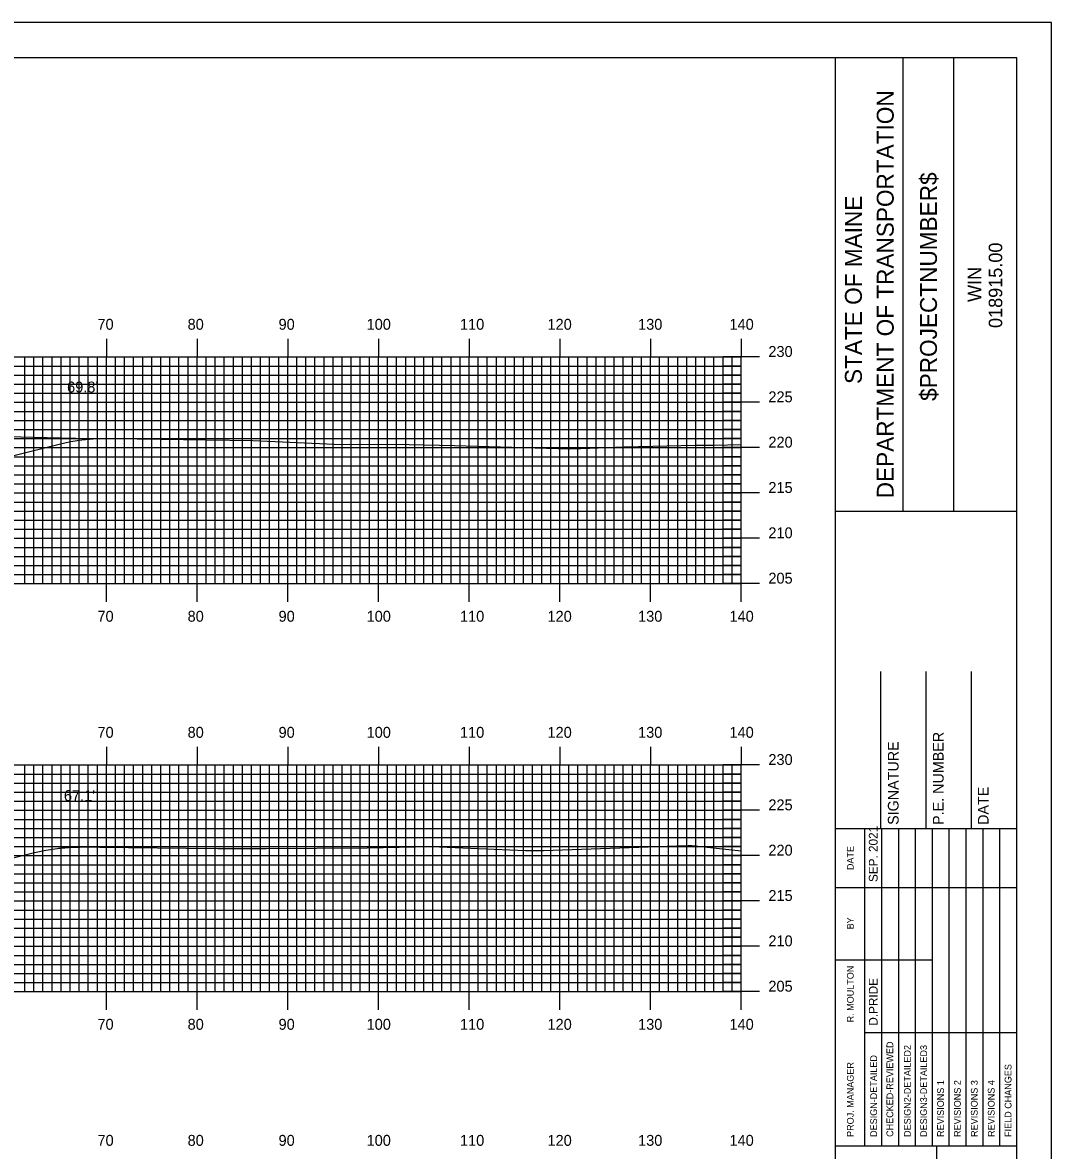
# Model space of a CAD drawing. Extents: x 1820424 to 1820768, y 442591 to 442811.
# Drawn here: x 1820650.9 to 1820764.4, y 442686.2 to 442810.5 of the extents above; entities that cross this region are included whole.
import ezdxf

# ---------------------------------------------------------------- set-up
doc = ezdxf.new("R2010")
doc.units = 0
for name, color, linetype in [('BORDER', 7, 'Continuous'), ('D_Roadway_Centerline', 7, 'Continuous'), ('D_Roadway_SlopeLines', 7, 'Continuous'), ('D_Text_Standard', 7, 'Continuous'), ('H_V ANNOTATION', 7, 'Continuous'), ('MAJOR', 7, 'Continuous'), ('MINOR', 7, 'Continuous'), ('PLOT BOUNDARY', 7, 'Continuous'), ('S_Roadway_Centerline', 7, 'Continuous')]:
    doc.layers.add(name, color=color, linetype=linetype)

msp = doc.modelspace()

# ---------------------------------------------------------------- linework, layer by layer
at = {"layer": 'BORDER'}
for p, q in [((1820740.6, 442596.67), (1820740.6, 442806.67)), ((1820748.06, 442756.66), (1820748.06, 442806.66)), ((1820753.65, 442756.66), (1820753.65, 442806.66)), ((1820740.61, 442756.65), (1820760.6, 442756.65)), ((1820745.6, 442721.67), (1820745.6, 442738.97)), ((1820750.6, 442721.67), (1820750.6, 442738.97)), ((1820755.6, 442721.67), (1820755.6, 442738.97)), ((1820740.6, 442721.67), (1820760.6, 442721.67)), ((1820740.6, 442686.67), (1820760.6, 442686.67)), ((1820751.79, 442616.67), (1820751.79, 442686.67))]:
    msp.add_line(p, q, dxfattribs=at)
msp.add_lwpolyline([(1820440.6, 442596.67), (1820760.6, 442596.67), (1820760.6, 442806.67), (1820440.6, 442806.67)], close=True, dxfattribs=at)
for points in [[(1820743.83, 442715.17), (1820743.83, 442721.67)], [(1820745.7, 442686.68), (1820745.7, 442721.67)], [(1820747.56, 442721.67), (1820747.56, 442686.68)], [(1820749.43, 442686.68), (1820749.43, 442721.67)], [(1820751.29, 442686.68), (1820751.29, 442721.67)], [(1820753.15, 442686.68), (1820753.15, 442721.67)], [(1820755.02, 442686.68), (1820755.02, 442721.67)], [(1820756.88, 442686.68), (1820756.88, 442721.67)], [(1820758.74, 442686.68), (1820758.74, 442721.67)], [(1820743.84, 442686.68), (1820743.84, 442720.26)], [(1820740.6, 442715.17), (1820760.6, 442715.17)], [(1820740.6, 442707.17), (1820743.84, 442707.17)], [(1820743.83, 442707.17), (1820751.29, 442707.17)], [(1820743.83, 442699.17), (1820760.6, 442699.17)]]:
    msp.add_lwpolyline(points, dxfattribs=at)
at = {"layer": 'D_Roadway_Centerline'}
for points in [[(1820513.87, 442766.87), (1820515.12, 442766.81), (1820516.37, 442766.67), (1820517.62, 442766.46), (1820518.87, 442766.19), (1820556.03, 442756.9), (1820560.03, 442757.9), (1820570.2, 442760.44), (1820578.2, 442760.76), (1820590.2, 442761), (1820602.2, 442760.76), (1820612.2, 442760.36), (1820622.2, 442757.86), (1820626.2, 442756.86), (1820654.98, 442764.06), (1820656.23, 442764.33), (1820657.48, 442764.52), (1820658.73, 442764.63), (1820659.98, 442764.66)], [(1820513.66, 442722.46), (1820514.91, 442722.44), (1820516.16, 442722.33), (1820517.41, 442722.14), (1820518.66, 442721.87), (1820556.03, 442712.52), (1820560.03, 442713.52), (1820570.2, 442716.07), (1820578.2, 442716.39), (1820590.2, 442716.63), (1820602.2, 442716.39), (1820612.2, 442715.99), (1820622.2, 442713.49), (1820626.2, 442712.49), (1820652.27, 442719), (1820653.52, 442719.27), (1820654.77, 442719.47), (1820656.02, 442719.58), (1820657.27, 442719.62)]]:
    msp.add_lwpolyline(points, dxfattribs=at)
at = {"layer": 'D_Roadway_SlopeLines'}
for points in [[(1820626.2, 442756.86), (1820654.98, 442764.06), (1820656.23, 442764.33), (1820657.48, 442764.52), (1820658.73, 442764.63), (1820659.98, 442764.66)], [(1820626.2, 442712.49), (1820652.27, 442719), (1820653.52, 442719.27), (1820654.77, 442719.47), (1820656.02, 442719.58), (1820657.27, 442719.62)]]:
    msp.add_lwpolyline(points, dxfattribs=at)
at = {"layer": 'MAJOR'}
for p, q in [((1820660.2, 442775.67), (1820660.2, 442773.67)), ((1820670.2, 442775.67), (1820670.2, 442773.67)), ((1820680.2, 442775.67), (1820680.2, 442773.67)), ((1820690.2, 442775.67), (1820690.2, 442773.67)), ((1820700.2, 442775.67), (1820700.2, 442773.67)), ((1820710.2, 442775.67), (1820710.2, 442773.67)), ((1820720.2, 442775.67), (1820720.2, 442773.67)), ((1820730.2, 442775.67), (1820730.2, 442773.67)), ((1820450.2, 442773.67), (1820730.2, 442773.67)), ((1820450.2, 442773.67), (1820730.2, 442773.67)), ((1820660.2, 442748.67), (1820660.2, 442773.67)), ((1820670.2, 442748.67), (1820670.2, 442773.67)), ((1820680.2, 442748.67), (1820680.2, 442773.67)), ((1820690.2, 442748.67), (1820690.2, 442773.67)), ((1820700.2, 442748.67), (1820700.2, 442773.67)), ((1820710.2, 442748.67), (1820710.2, 442773.67)), ((1820720.2, 442748.67), (1820720.2, 442773.67)), ((1820732.21, 442773.67), (1820728.2, 442773.67)), ((1820730.2, 442748.67), (1820730.2, 442773.67)), ((1820730.2, 442748.67), (1820730.2, 442773.67)), ((1820450.2, 442768.67), (1820730.2, 442768.67)), ((1820732.21, 442768.67), (1820728.2, 442768.67)), ((1820450.2, 442763.67), (1820730.2, 442763.67)), ((1820732.21, 442763.67), (1820728.2, 442763.67)), ((1820450.2, 442758.67), (1820730.2, 442758.67)), ((1820732.21, 442758.67), (1820728.2, 442758.67)), ((1820450.2, 442753.67), (1820730.2, 442753.67)), ((1820732.21, 442753.67), (1820728.2, 442753.67)), ((1820450.2, 442748.67), (1820730.2, 442748.67)), ((1820450.2, 442748.67), (1820730.2, 442748.67)), ((1820660.2, 442746.66), (1820660.2, 442748.67)), ((1820670.2, 442746.66), (1820670.2, 442748.67)), ((1820680.2, 442746.66), (1820680.2, 442748.67)), ((1820690.2, 442746.66), (1820690.2, 442748.67)), ((1820700.2, 442746.66), (1820700.2, 442748.67)), ((1820710.2, 442746.66), (1820710.2, 442748.67)), ((1820720.2, 442746.66), (1820720.2, 442748.67)), ((1820732.21, 442748.67), (1820728.2, 442748.67)), ((1820730.2, 442746.66), (1820730.2, 442748.67)), ((1820660.2, 442730.67), (1820660.2, 442728.67)), ((1820670.2, 442730.67), (1820670.2, 442728.67)), ((1820680.2, 442730.67), (1820680.2, 442728.67)), ((1820690.2, 442730.67), (1820690.2, 442728.67)), ((1820700.2, 442730.67), (1820700.2, 442728.67)), ((1820710.2, 442730.67), (1820710.2, 442728.67)), ((1820720.2, 442730.67), (1820720.2, 442728.67)), ((1820730.2, 442730.67), (1820730.2, 442728.67)), ((1820450.2, 442728.67), (1820730.2, 442728.67)), ((1820450.2, 442728.67), (1820730.2, 442728.67)), ((1820660.2, 442703.67), (1820660.2, 442728.67)), ((1820670.2, 442703.67), (1820670.2, 442728.67)), ((1820680.2, 442703.67), (1820680.2, 442728.67)), ((1820690.2, 442703.67), (1820690.2, 442728.67)), ((1820700.2, 442703.67), (1820700.2, 442728.67)), ((1820710.2, 442703.67), (1820710.2, 442728.67)), ((1820720.2, 442703.67), (1820720.2, 442728.67)), ((1820732.21, 442728.67), (1820728.2, 442728.67)), ((1820730.2, 442703.67), (1820730.2, 442728.67)), ((1820730.2, 442703.67), (1820730.2, 442728.67)), ((1820450.2, 442723.67), (1820730.2, 442723.67)), ((1820732.21, 442723.67), (1820728.2, 442723.67)), ((1820450.2, 442718.67), (1820730.2, 442718.67)), ((1820732.21, 442718.67), (1820728.2, 442718.67)), ((1820450.2, 442713.67), (1820730.2, 442713.67)), ((1820732.21, 442713.67), (1820728.2, 442713.67)), ((1820450.2, 442708.67), (1820730.2, 442708.67)), ((1820732.21, 442708.67), (1820728.2, 442708.67)), ((1820450.2, 442703.67), (1820730.2, 442703.67)), ((1820450.2, 442703.67), (1820730.2, 442703.67)), ((1820660.2, 442701.66), (1820660.2, 442703.67)), ((1820670.2, 442701.66), (1820670.2, 442703.67)), ((1820680.2, 442701.66), (1820680.2, 442703.67)), ((1820690.2, 442701.66), (1820690.2, 442703.67)), ((1820700.2, 442701.66), (1820700.2, 442703.67)), ((1820710.2, 442701.66), (1820710.2, 442703.67)), ((1820720.2, 442701.66), (1820720.2, 442703.67)), ((1820732.21, 442703.67), (1820728.2, 442703.67)), ((1820730.2, 442701.66), (1820730.2, 442703.67))]:
    msp.add_line(p, q, dxfattribs=at)
at = {"layer": 'MINOR'}
for p, q in [((1820651.2, 442748.67), (1820651.2, 442773.67)), ((1820652.2, 442748.67), (1820652.2, 442773.67)), ((1820653.2, 442748.67), (1820653.2, 442773.67)), ((1820654.2, 442748.67), (1820654.2, 442773.67)), ((1820655.2, 442748.67), (1820655.2, 442773.67)), ((1820656.2, 442748.67), (1820656.2, 442773.67)), ((1820657.2, 442748.67), (1820657.2, 442773.67)), ((1820658.2, 442748.67), (1820658.2, 442773.67)), ((1820659.2, 442748.67), (1820659.2, 442773.67)), ((1820661.2, 442748.67), (1820661.2, 442773.67)), ((1820662.2, 442748.67), (1820662.2, 442773.67)), ((1820663.2, 442748.67), (1820663.2, 442773.67)), ((1820664.2, 442748.67), (1820664.2, 442773.67)), ((1820665.2, 442748.67), (1820665.2, 442773.67)), ((1820666.2, 442748.67), (1820666.2, 442773.67)), ((1820667.2, 442748.67), (1820667.2, 442773.67)), ((1820668.2, 442748.67), (1820668.2, 442773.67)), ((1820669.2, 442748.67), (1820669.2, 442773.67)), ((1820671.2, 442748.67), (1820671.2, 442773.67)), ((1820672.2, 442748.67), (1820672.2, 442773.67)), ((1820673.2, 442748.67), (1820673.2, 442773.67)), ((1820674.2, 442748.67), (1820674.2, 442773.67)), ((1820675.2, 442748.67), (1820675.2, 442773.67)), ((1820676.2, 442748.67), (1820676.2, 442773.67)), ((1820677.2, 442748.67), (1820677.2, 442773.67)), ((1820678.2, 442748.67), (1820678.2, 442773.67)), ((1820679.2, 442748.67), (1820679.2, 442773.67)), ((1820681.2, 442748.67), (1820681.2, 442773.67)), ((1820682.2, 442748.67), (1820682.2, 442773.67)), ((1820683.2, 442748.67), (1820683.2, 442773.67)), ((1820684.2, 442748.67), (1820684.2, 442773.67)), ((1820685.2, 442748.67), (1820685.2, 442773.67)), ((1820686.2, 442748.67), (1820686.2, 442773.67)), ((1820687.2, 442748.67), (1820687.2, 442773.67)), ((1820688.2, 442748.67), (1820688.2, 442773.67)), ((1820689.2, 442748.67), (1820689.2, 442773.67)), ((1820691.2, 442748.67), (1820691.2, 442773.67)), ((1820692.2, 442748.67), (1820692.2, 442773.67)), ((1820693.2, 442748.67), (1820693.2, 442773.67)), ((1820694.2, 442748.67), (1820694.2, 442773.67)), ((1820695.2, 442748.67), (1820695.2, 442773.67)), ((1820696.2, 442748.67), (1820696.2, 442773.67)), ((1820697.2, 442748.67), (1820697.2, 442773.67)), ((1820698.2, 442748.67), (1820698.2, 442773.67)), ((1820699.2, 442748.67), (1820699.2, 442773.67)), ((1820701.2, 442748.67), (1820701.2, 442773.67)), ((1820702.2, 442748.67), (1820702.2, 442773.67)), ((1820703.2, 442748.67), (1820703.2, 442773.67)), ((1820704.2, 442748.67), (1820704.2, 442773.67)), ((1820705.2, 442748.67), (1820705.2, 442773.67)), ((1820706.2, 442748.67), (1820706.2, 442773.67)), ((1820707.2, 442748.67), (1820707.2, 442773.67)), ((1820708.2, 442748.67), (1820708.2, 442773.67)), ((1820709.2, 442748.67), (1820709.2, 442773.67)), ((1820711.2, 442748.67), (1820711.2, 442773.67)), ((1820712.2, 442748.67), (1820712.2, 442773.67)), ((1820713.2, 442748.67), (1820713.2, 442773.67)), ((1820714.2, 442748.67), (1820714.2, 442773.67)), ((1820715.2, 442748.67), (1820715.2, 442773.67)), ((1820716.2, 442748.67), (1820716.2, 442773.67)), ((1820717.2, 442748.67), (1820717.2, 442773.67)), ((1820718.2, 442748.67), (1820718.2, 442773.67)), ((1820719.2, 442748.67), (1820719.2, 442773.67)), ((1820721.2, 442748.67), (1820721.2, 442773.67)), ((1820722.2, 442748.67), (1820722.2, 442773.67)), ((1820723.2, 442748.67), (1820723.2, 442773.67)), ((1820724.2, 442748.67), (1820724.2, 442773.67)), ((1820725.2, 442748.67), (1820725.2, 442773.67)), ((1820726.2, 442748.67), (1820726.2, 442773.67)), ((1820727.2, 442748.67), (1820727.2, 442773.67)), ((1820728.2, 442748.67), (1820728.2, 442773.67)), ((1820729.2, 442748.67), (1820729.2, 442773.67)), ((1820450.2, 442772.67), (1820730.2, 442772.67)), ((1820730.2, 442772.67), (1820728.2, 442772.67)), ((1820450.2, 442771.67), (1820730.2, 442771.67)), ((1820730.2, 442771.67), (1820728.2, 442771.67)), ((1820450.2, 442770.67), (1820730.2, 442770.67)), ((1820730.2, 442770.67), (1820728.2, 442770.67)), ((1820450.2, 442769.67), (1820730.2, 442769.67)), ((1820730.2, 442769.67), (1820728.2, 442769.67)), ((1820450.2, 442767.67), (1820730.2, 442767.67)), ((1820730.2, 442767.67), (1820728.2, 442767.67)), ((1820450.2, 442766.67), (1820730.2, 442766.67)), ((1820730.2, 442766.67), (1820728.2, 442766.67)), ((1820450.2, 442765.67), (1820730.2, 442765.67)), ((1820730.2, 442765.67), (1820728.2, 442765.67)), ((1820450.2, 442764.67), (1820730.2, 442764.67)), ((1820730.2, 442764.67), (1820728.2, 442764.67)), ((1820450.2, 442762.67), (1820730.2, 442762.67)), ((1820730.2, 442762.67), (1820728.2, 442762.67)), ((1820450.2, 442761.67), (1820730.2, 442761.67)), ((1820730.2, 442761.67), (1820728.2, 442761.67)), ((1820450.2, 442760.67), (1820730.2, 442760.67)), ((1820730.2, 442760.67), (1820728.2, 442760.67)), ((1820450.2, 442759.67), (1820730.2, 442759.67)), ((1820730.2, 442759.67), (1820728.2, 442759.67)), ((1820450.2, 442757.67), (1820730.2, 442757.67)), ((1820730.2, 442757.67), (1820728.2, 442757.67)), ((1820450.2, 442756.67), (1820730.2, 442756.67)), ((1820730.2, 442756.67), (1820728.2, 442756.67)), ((1820450.2, 442755.67), (1820730.2, 442755.67)), ((1820730.2, 442755.67), (1820728.2, 442755.67)), ((1820450.2, 442754.67), (1820730.2, 442754.67)), ((1820730.2, 442754.67), (1820728.2, 442754.67)), ((1820450.2, 442752.67), (1820730.2, 442752.67)), ((1820730.2, 442752.67), (1820728.2, 442752.67)), ((1820450.2, 442751.67), (1820730.2, 442751.67)), ((1820730.2, 442751.67), (1820728.2, 442751.67)), ((1820450.2, 442750.67), (1820730.2, 442750.67)), ((1820730.2, 442750.67), (1820728.2, 442750.67)), ((1820450.2, 442749.67), (1820730.2, 442749.67)), ((1820730.2, 442749.67), (1820728.2, 442749.67)), ((1820450.2, 442727.67), (1820730.2, 442727.67)), ((1820651.2, 442703.67), (1820651.2, 442728.67)), ((1820652.2, 442703.67), (1820652.2, 442728.67)), ((1820653.2, 442703.67), (1820653.2, 442728.67)), ((1820654.2, 442703.67), (1820654.2, 442728.67)), ((1820655.2, 442703.67), (1820655.2, 442728.67)), ((1820656.2, 442703.67), (1820656.2, 442728.67)), ((1820657.2, 442703.67), (1820657.2, 442728.67)), ((1820658.2, 442703.67), (1820658.2, 442728.67)), ((1820659.2, 442703.67), (1820659.2, 442728.67)), ((1820661.2, 442703.67), (1820661.2, 442728.67)), ((1820662.2, 442703.67), (1820662.2, 442728.67)), ((1820663.2, 442703.67), (1820663.2, 442728.67)), ((1820664.2, 442703.67), (1820664.2, 442728.67)), ((1820665.2, 442703.67), (1820665.2, 442728.67)), ((1820666.2, 442703.67), (1820666.2, 442728.67)), ((1820667.2, 442703.67), (1820667.2, 442728.67)), ((1820668.2, 442703.67), (1820668.2, 442728.67)), ((1820669.2, 442703.67), (1820669.2, 442728.67)), ((1820671.2, 442703.67), (1820671.2, 442728.67)), ((1820672.2, 442703.67), (1820672.2, 442728.67)), ((1820673.2, 442703.67), (1820673.2, 442728.67)), ((1820674.2, 442703.67), (1820674.2, 442728.67)), ((1820675.2, 442703.67), (1820675.2, 442728.67)), ((1820676.2, 442703.67), (1820676.2, 442728.67)), ((1820677.2, 442703.67), (1820677.2, 442728.67)), ((1820678.2, 442703.67), (1820678.2, 442728.67)), ((1820679.2, 442703.67), (1820679.2, 442728.67)), ((1820681.2, 442703.67), (1820681.2, 442728.67)), ((1820682.2, 442703.67), (1820682.2, 442728.67)), ((1820683.2, 442703.67), (1820683.2, 442728.67)), ((1820684.2, 442703.67), (1820684.2, 442728.67)), ((1820685.2, 442703.67), (1820685.2, 442728.67)), ((1820686.2, 442703.67), (1820686.2, 442728.67)), ((1820687.2, 442703.67), (1820687.2, 442728.67)), ((1820688.2, 442703.67), (1820688.2, 442728.67)), ((1820689.2, 442703.67), (1820689.2, 442728.67)), ((1820691.2, 442703.67), (1820691.2, 442728.67)), ((1820692.2, 442703.67), (1820692.2, 442728.67)), ((1820693.2, 442703.67), (1820693.2, 442728.67)), ((1820694.2, 442703.67), (1820694.2, 442728.67)), ((1820695.2, 442703.67), (1820695.2, 442728.67)), ((1820696.2, 442703.67), (1820696.2, 442728.67)), ((1820697.2, 442703.67), (1820697.2, 442728.67)), ((1820698.2, 442703.67), (1820698.2, 442728.67)), ((1820699.2, 442703.67), (1820699.2, 442728.67)), ((1820701.2, 442703.67), (1820701.2, 442728.67)), ((1820702.2, 442703.67), (1820702.2, 442728.67)), ((1820703.2, 442703.67), (1820703.2, 442728.67)), ((1820704.2, 442703.67), (1820704.2, 442728.67)), ((1820705.2, 442703.67), (1820705.2, 442728.67)), ((1820706.2, 442703.67), (1820706.2, 442728.67)), ((1820707.2, 442703.67), (1820707.2, 442728.67)), ((1820708.2, 442703.67), (1820708.2, 442728.67)), ((1820709.2, 442703.67), (1820709.2, 442728.67)), ((1820711.2, 442703.67), (1820711.2, 442728.67)), ((1820712.2, 442703.67), (1820712.2, 442728.67)), ((1820713.2, 442703.67), (1820713.2, 442728.67)), ((1820714.2, 442703.67), (1820714.2, 442728.67)), ((1820715.2, 442703.67), (1820715.2, 442728.67)), ((1820716.2, 442703.67), (1820716.2, 442728.67)), ((1820717.2, 442703.67), (1820717.2, 442728.67)), ((1820718.2, 442703.67), (1820718.2, 442728.67)), ((1820719.2, 442703.67), (1820719.2, 442728.67)), ((1820721.2, 442703.67), (1820721.2, 442728.67)), ((1820722.2, 442703.67), (1820722.2, 442728.67)), ((1820723.2, 442703.67), (1820723.2, 442728.67)), ((1820724.2, 442703.67), (1820724.2, 442728.67)), ((1820725.2, 442703.67), (1820725.2, 442728.67)), ((1820726.2, 442703.67), (1820726.2, 442728.67)), ((1820727.2, 442703.67), (1820727.2, 442728.67)), ((1820728.2, 442703.67), (1820728.2, 442728.67)), ((1820730.2, 442727.67), (1820728.2, 442727.67)), ((1820729.2, 442703.67), (1820729.2, 442728.67)), ((1820450.2, 442726.67), (1820730.2, 442726.67)), ((1820730.2, 442726.67), (1820728.2, 442726.67)), ((1820450.2, 442725.67), (1820730.2, 442725.67)), ((1820730.2, 442725.67), (1820728.2, 442725.67)), ((1820450.2, 442724.67), (1820730.2, 442724.67)), ((1820730.2, 442724.67), (1820728.2, 442724.67)), ((1820450.2, 442722.67), (1820730.2, 442722.67)), ((1820730.2, 442722.67), (1820728.2, 442722.67)), ((1820450.2, 442721.67), (1820730.2, 442721.67)), ((1820730.2, 442721.67), (1820728.2, 442721.67)), ((1820450.2, 442720.67), (1820730.2, 442720.67)), ((1820730.2, 442720.67), (1820728.2, 442720.67)), ((1820450.2, 442719.67), (1820730.2, 442719.67)), ((1820730.2, 442719.67), (1820728.2, 442719.67)), ((1820450.2, 442717.67), (1820730.2, 442717.67)), ((1820730.2, 442717.67), (1820728.2, 442717.67)), ((1820450.2, 442716.67), (1820730.2, 442716.67)), ((1820730.2, 442716.67), (1820728.2, 442716.67)), ((1820450.2, 442715.67), (1820730.2, 442715.67)), ((1820730.2, 442715.67), (1820728.2, 442715.67)), ((1820450.2, 442714.67), (1820730.2, 442714.67)), ((1820730.2, 442714.67), (1820728.2, 442714.67)), ((1820450.2, 442712.67), (1820730.2, 442712.67)), ((1820730.2, 442712.67), (1820728.2, 442712.67)), ((1820450.2, 442711.67), (1820730.2, 442711.67)), ((1820730.2, 442711.67), (1820728.2, 442711.67)), ((1820450.2, 442710.67), (1820730.2, 442710.67)), ((1820730.2, 442710.67), (1820728.2, 442710.67)), ((1820450.2, 442709.67), (1820730.2, 442709.67)), ((1820730.2, 442709.67), (1820728.2, 442709.67)), ((1820450.2, 442707.67), (1820730.2, 442707.67)), ((1820450.2, 442706.67), (1820730.2, 442706.67)), ((1820730.2, 442707.67), (1820728.2, 442707.67)), ((1820730.2, 442706.67), (1820728.2, 442706.67)), ((1820450.2, 442705.67), (1820730.2, 442705.67)), ((1820730.2, 442705.67), (1820728.2, 442705.67)), ((1820450.2, 442704.67), (1820730.2, 442704.67)), ((1820730.2, 442704.67), (1820728.2, 442704.67))]:
    msp.add_line(p, q, dxfattribs=at)
at = {"layer": 'PLOT BOUNDARY'}
msp.add_lwpolyline([(1820424.42, 442590.55), (1820764.42, 442590.55), (1820764.42, 442810.55), (1820424.42, 442810.55)], close=True, dxfattribs=at)
at = {"layer": 'S_Roadway_Centerline'}
for points in [[(1820642, 442765.07), (1820655.12, 442764.74), (1820658.52, 442764.66), (1820659.44, 442764.65), (1820661.03, 442764.67), (1820676.33, 442764.45), (1820685.31, 442764.06), (1820693.6, 442764.02), (1820698.6, 442763.92), (1820711.25, 442763.54), (1820712.51, 442763.56), (1820717.3, 442763.76), (1820725.17, 442763.94), (1820727.24, 442763.95), (1820730.2, 442764)], [(1820627.75, 442719.67), (1820654.9, 442719.63), (1820655.26, 442719.63), (1820656.26, 442719.63), (1820668.99, 442719.5), (1820672.48, 442719.45), (1820677.83, 442719.45), (1820688.95, 442719.53), (1820696.06, 442719.68), (1820706.41, 442719.24), (1820708.39, 442719.22), (1820723.1, 442719.77), (1820724.36, 442719.8), (1820724.77, 442719.78), (1820730.2, 442719.21)]]:
    msp.add_lwpolyline(points, dxfattribs=at)

# ---------------------------------------------------------------- texts
at = {"layer": 'BORDER'}
for s, height, p in [('DEPARTMENT OF TRANSPORTATION', 1.8635, (1820747.02, 442758.08)), ('$PROJECTNUMBER$', 1.8635, (1820751.79, 442768.82)), ('STATE OF MAINE', 1.8635, (1820743.51, 442770.69)), ('018915.00', 1.491, (1820758.99, 442776.86)), ('WIN', 1.491, (1820756.68, 442779.73)), ('P.E. NUMBER', 1.1811, (1820752.53, 442722.06)), ('SIGNATURE', 1.181, (1820747.56, 442722.06)), ('DATE', 1.181, (1820757.49, 442722.06)), ('SEP. 2021', 0.969, (1820745.25, 442715.76)), ('DATE', 0.743, (1820742.61, 442717.08)), ('BY', 0.743, (1820742.61, 442710.54)), ('R. MOULTON', 0.745, (1820742.61, 442700.28)), ('D.PRIDE', 0.969, (1820745.25, 442699.92)), ('CHECKED-REVIEWED', 0.7455, (1820746.97, 442687.65)), ('DESIGN2-DETAILED2', 0.7455, (1820748.9, 442687.65)), ('DESIGN3-DETAILED3', 0.7455, (1820750.69, 442687.65)), ('DESIGN-DETAILED', 0.7455, (1820745.18, 442687.65)), ('PROJ. MANAGER', 0.7455, (1820742.61, 442687.65)), ('FIELD CHANGES', 0.7455, (1820760.01, 442687.65)), ('REVISIONS 1', 0.7455, (1820752.56, 442687.65)), ('REVISIONS 2', 0.7455, (1820754.42, 442687.65)), ('REVISIONS 3', 0.7455, (1820756.28, 442687.65)), ('REVISIONS 4', 0.7455, (1820758.15, 442687.65))]:
    msp.add_text(s, height=height, rotation=90, dxfattribs=at).set_placement(p)
at = {"layer": 'D_Text_Standard'}
for s, p in [("69.8'", (1820655.86, 442769.75)), ("67.1'", (1820655.51, 442724.69))]:
    msp.add_text(s, height=1.2, dxfattribs=at).set_placement(p)
at = {"layer": 'H_V ANNOTATION'}
for s, p in [('70', (1820659.21, 442776.67)), ('80', (1820669.15, 442776.67)), ('90', (1820679.18, 442776.67)), ('100', (1820688.89, 442776.67)), ('110', (1820699.19, 442776.67)), ('120', (1820708.84, 442776.67)), ('130', (1820718.83, 442776.67)), ('140', (1820728.91, 442776.67)), ('230', (1820733.2, 442773.67)), ('225', (1820733.2, 442768.67)), ('220', (1820733.2, 442763.67)), ('215', (1820733.2, 442758.67)), ('210', (1820733.2, 442753.67)), ('205', (1820733.2, 442748.67)), ('70', (1820659.21, 442744.47)), ('80', (1820669.15, 442744.47)), ('90', (1820679.18, 442744.47)), ('100', (1820688.89, 442744.47)), ('110', (1820699.19, 442744.47)), ('120', (1820708.84, 442744.47)), ('130', (1820718.83, 442744.47)), ('140', (1820728.91, 442744.47)), ('70', (1820659.21, 442731.67)), ('80', (1820669.15, 442731.67)), ('90', (1820679.18, 442731.67)), ('100', (1820688.89, 442731.67)), ('110', (1820699.19, 442731.67)), ('120', (1820708.84, 442731.67)), ('130', (1820718.83, 442731.67)), ('140', (1820728.91, 442731.67)), ('230', (1820733.2, 442728.67)), ('225', (1820733.2, 442723.67)), ('220', (1820733.2, 442718.67)), ('215', (1820733.2, 442713.67)), ('210', (1820733.2, 442708.67)), ('205', (1820733.2, 442703.67)), ('70', (1820659.21, 442699.47)), ('80', (1820669.15, 442699.47)), ('90', (1820679.18, 442699.47)), ('100', (1820688.89, 442699.47)), ('110', (1820699.19, 442699.47)), ('120', (1820708.84, 442699.47)), ('130', (1820718.83, 442699.47)), ('140', (1820728.91, 442699.47)), ('70', (1820659.21, 442686.67)), ('80', (1820669.15, 442686.67)), ('90', (1820679.18, 442686.67)), ('100', (1820688.89, 442686.67)), ('110', (1820699.19, 442686.67)), ('120', (1820708.84, 442686.67)), ('130', (1820718.83, 442686.67)), ('140', (1820728.91, 442686.67))]:
    msp.add_text(s, height=1.2, dxfattribs=at).set_placement(p)

doc.saveas('drawing.dxf')
